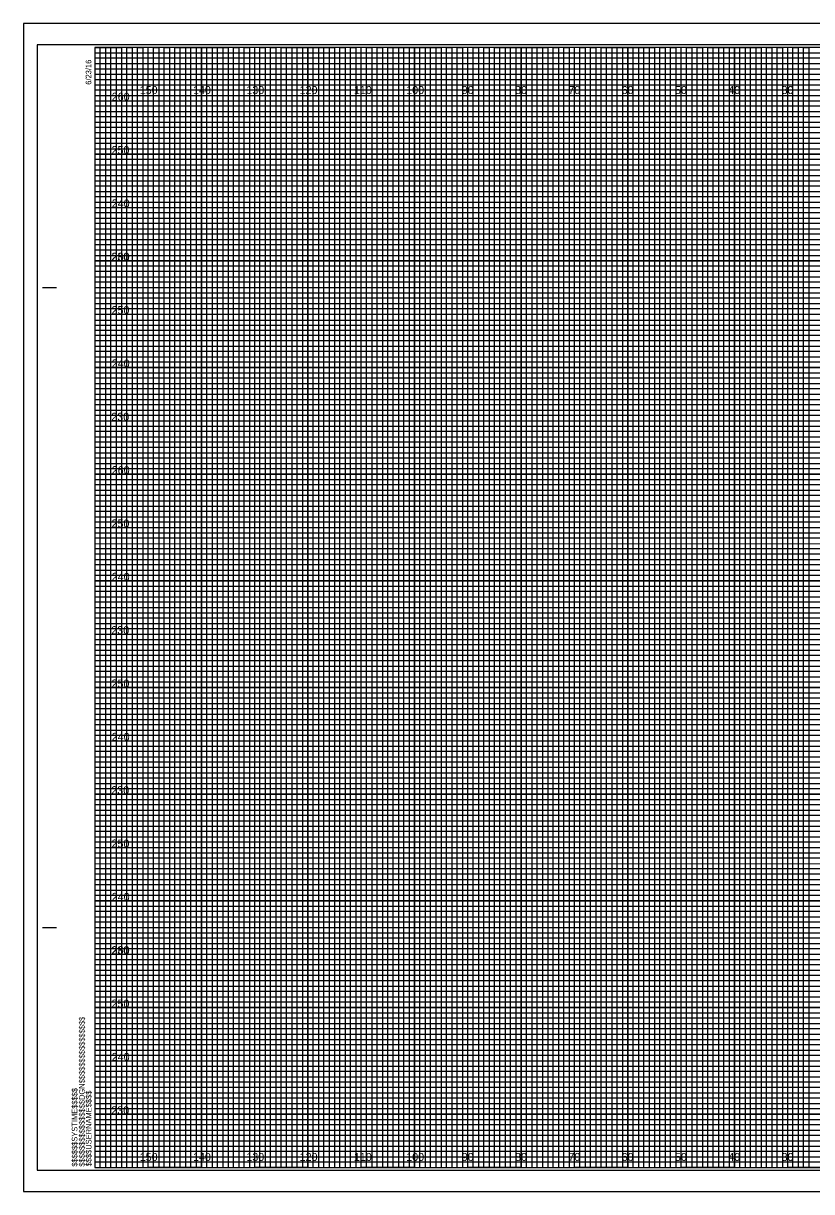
# Model space of a CAD drawing. Extents: x -13 to 359, y -5 to 2854.
# Drawn here: x -13.4 to 134.5, y 655.5 to 874.5 of the extents above; entities that cross this region are included whole.
import ezdxf

# ---------------------------------------------------------------- set-up
doc = ezdxf.new("R2010")
doc.units = 0
for name, color, linetype in [('Exist Cross Section Cell', 7, 'Continuous'), ('Exist XS Ground Line', 7, 'Continuous'), ('Prop CMT Concrete Structures', 7, 'Continuous'), ('Prop CMT DNC', 7, 'Continuous'), ('Prop CMT Pvmt Course 1', 7, 'Continuous'), ('Prop CMT Pvmt Course 1 CG', 7, 'Continuous'), ('Prop CMT Pvmt Course 2', 7, 'Continuous'), ('Prop CMT Shear Line', 7, 'Continuous'), ('Prop CMT Slope Grass', 7, 'Continuous'), ('Prop CMT Subgrade Earthwork', 7, 'Continuous'), ('Scratch_Level_0', 7, 'Continuous')]:
    doc.layers.add(name, color=color, linetype=linetype)

msp = doc.modelspace()

# ---------------------------------------------------------------- linework, layer by layer
at = {"layer": 'Exist XS Ground Line'}
for p, q in [((10, 870), (0, 870)), ((10, 660), (10, 870)), ((30, 870), (20, 870)), ((20, 870), (20, 660)), ((30, 660), (30, 870)), ((50, 870), (40, 870)), ((40, 870), (40, 660)), ((50, 660), (50, 870)), ((70, 870), (60, 870)), ((60, 870), (60, 660)), ((70, 660), (70, 870)), ((90, 870), (80, 870)), ((80, 870), (80, 660)), ((90, 660), (90, 870)), ((110, 870), (100, 870)), ((100, 870), (100, 660)), ((110, 660), (110, 870)), ((130, 870), (120, 870)), ((120, 870), (120, 660)), ((130, 660), (130, 870)), ((20, 660), (10, 660)), ((40, 660), (30, 660)), ((60, 660), (50, 660)), ((80, 660), (70, 660)), ((100, 660), (90, 660)), ((120, 660), (110, 660)), ((140, 660), (130, 660))]:
    msp.add_line(p, q, dxfattribs=at)
for points in [[(0, 860), (320, 860), (320, 850), (0, 850)], [(0, 840), (320, 840), (320, 830), (0, 830)], [(0, 820), (320, 820), (320, 810), (0, 810)], [(0, 800), (320, 800), (320, 790), (0, 790)], [(0, 780), (320, 780), (320, 770), (0, 770)], [(0, 760), (320, 760), (320, 750), (0, 750)], [(0, 740), (320, 740), (320, 730), (0, 730)], [(0, 720), (320, 720), (320, 710), (0, 710)], [(0, 700), (320, 700), (320, 690), (0, 690)], [(0, 680), (320, 680), (320, 670), (0, 670)]]:
    msp.add_lwpolyline(points, dxfattribs=at)
at = {"layer": 'Prop CMT Concrete Structures'}
for p, q in [((-9.8, 825), (-7.3, 825)), ((-9.7, 825), (-7.2, 825)), ((-9.8, 705), (-7.3, 705)), ((-9.7, 705), (-7.2, 705)), ((0, 660), (0, 660)), ((0, 660), (0, 660)), ((0, 660), (0, 660)), ((0, 660), (0, 660)), ((0, 660), (0, 660)), ((0, 660), (0, 660)), ((0, 660), (0, 660))]:
    msp.add_line(p, q, dxfattribs=at)
msp.add_lwpolyline([(320, 870), (0, 870), (0, 660), (320, 660)], close=True, dxfattribs=at)
at = {"layer": 'Prop CMT DNC'}
for p, q in [((323.3, 874.5), (-13.4, 874.5)), ((-13.4, 874.5), (-13.4, 655.5)), ((-13.4, 655.5), (323.3, 655.5))]:
    msp.add_line(p, q, dxfattribs=at)
at = {"layer": 'Prop CMT Pvmt Course 1'}
for p, q in [((0, 869), (260, 869)), ((260, 867.98), (0, 867.98)), ((0, 867.98), (0, 867)), ((0, 867), (260, 867)), ((260, 865.89), (0, 865.89)), ((0, 865.89), (0, 864)), ((0, 864), (320, 864))]:
    msp.add_line(p, q, dxfattribs=at)
for points in [[(0, 863), (270, 863), (320, 863), (320, 862), (0, 862)], [(0, 861), (320, 861), (320, 859), (0, 859)], [(0, 858), (320, 858), (320, 857), (0, 856.98)], [(0, 856), (320, 856), (320, 854), (0, 854)], [(0, 853), (320, 853), (320, 852), (0, 852)], [(0, 851), (320, 851), (320, 849), (0, 849)], [(0, 848), (320, 848), (320, 847), (0, 847)], [(0, 846), (320, 846), (320, 844), (0, 844)], [(0, 843), (320, 843), (320, 842), (0, 842)], [(0, 841), (320, 841), (320, 839), (0, 839)], [(0, 838), (320, 838), (320, 837), (0, 837)], [(0, 836), (320, 836), (320, 833.95), (320, 833), (320, 832), (0, 832)], [(0, 834), (320, 834), (320, 833), (0, 833)], [(0, 831), (320, 831), (320, 829), (0, 829.03)], [(0, 829.03), (320, 829), (320, 828), (0, 828)], [(0, 827), (320, 827), (320, 826), (0, 826)], [(0, 824), (320, 824), (320, 823), (0, 823)], [(0, 822), (320, 822), (320, 821), (0, 821)], [(-0.07, 818.89), (320, 818.89), (320, 817.88), (-0.07, 817.88)], [(0, 817), (320, 817), (320, 816), (0, 816)], [(0, 814), (320, 814), (320, 813), (0, 813)], [(0, 812), (320, 812), (320, 811), (0, 811)], [(0, 809), (320, 809), (320, 808), (0, 808)], [(0, 807), (320, 807), (320, 806), (0, 806)], [(0, 804), (320, 804), (320, 803), (0, 803)], [(0, 802), (320, 802), (320, 801), (0, 801)], [(0, 799), (320, 799), (319.99, 797.98), (0, 798)], [(0, 797), (320, 797), (320, 796), (0, 796)], [(0, 794), (320, 794), (320, 793), (0, 793)], [(0, 792), (320, 792), (320, 791), (0, 791)], [(0, 789), (320, 789), (320, 788), (0, 788)], [(0, 787), (320, 787), (320, 786), (0, 786)], [(0, 784), (320, 784), (320, 783), (0, 783)], [(0, 782), (320, 782), (320, 781), (0, 781)], [(0, 779), (320, 779), (320, 778), (0, 778)], [(0, 776.99), (320.07, 776.91), (320, 776), (0, 776)], [(0, 774), (320, 774), (320, 773), (0, 773)], [(0, 772), (320, 772), (320, 771), (0, 771)], [(0, 769), (320, 769), (320, 768), (0, 768)], [(0, 767), (320, 767), (320, 766), (0, 766)], [(0, 764), (320, 764), (320, 763), (0, 763)], [(0, 762), (320, 762), (320, 761), (0, 761)], [(0, 759), (320, 759), (320, 758), (0, 758)], [(0, 757), (320, 757), (320, 756), (0, 756)], [(0, 754), (320, 754), (320, 753), (0, 753)], [(0, 752), (320, 752), (320, 751), (0, 751)], [(0, 749), (320, 749), (320, 748), (0, 748)], [(0, 747), (320, 747), (320, 746), (0, 746)], [(0, 744), (320, 744), (320, 743), (0, 743)], [(0, 742), (320, 742), (320, 741), (0, 741)], [(0, 739), (320, 739), (319.99, 737.98), (0, 738)], [(0, 737), (320, 737), (320, 736), (0, 736)], [(0, 734), (320, 734), (320, 733), (0, 733)], [(0, 732), (320, 732), (320, 731), (0, 731)], [(0, 729), (320, 729), (320, 728), (0, 728)], [(0, 727), (320, 727), (320, 726), (0, 726)], [(0, 724), (320, 724), (320, 723), (0, 723)], [(0, 722), (320, 722), (320, 721), (0, 721)], [(0, 719), (320, 719), (320, 718), (0, 718)], [(0, 716.99), (320.07, 716.91), (320, 716), (0, 716)], [(0, 714), (320, 714), (320, 713), (0, 713)], [(0, 712), (320, 712), (320, 711), (0, 711)], [(0, 709), (320, 709), (320, 708), (0, 708)], [(0, 707), (320, 707), (320, 706), (0, 706)], [(0, 704), (320, 704), (320, 703), (0, 703)], [(0, 702), (320, 702), (320, 701), (0, 701)], [(0, 699), (320, 699), (320, 698), (0, 698)], [(0, 697), (320, 697), (320, 696), (0, 696)], [(0, 694), (320, 694), (320, 693), (0, 693)], [(0, 692), (320, 692), (320, 691), (0, 691)], [(0, 689), (320, 689), (320, 688), (0, 688)], [(0, 687), (320, 687), (320, 686), (0, 686)], [(0, 684), (320, 684), (320, 683), (0, 683)], [(0, 682), (320, 682), (320, 681), (0, 681)], [(0, 679), (320, 679), (320, 678), (0, 678)], [(0, 677), (320, 677), (320, 676), (0, 676)], [(0, 674), (320, 674), (320, 673), (0, 673)], [(0, 672), (320, 672), (320, 671), (0, 671)], [(0, 669), (320, 669), (320, 668), (0, 668)], [(0, 667), (320, 667), (320, 666), (0, 666)], [(0, 664), (320, 664), (320, 663), (0, 663)], [(0, 662), (320, 662), (320, 661), (0, 661)]]:
    msp.add_lwpolyline(points, dxfattribs=at)
at = {"layer": 'Prop CMT Pvmt Course 1 CG'}
for points in [[(0, 660), (1, 660), (1, 870), (2, 870), (2, 660)], [(2, 660), (3, 660), (3, 870), (4, 870), (4, 660)], [(5, 660), (6, 660), (6, 870), (7, 870), (7, 660)], [(7, 660), (8, 660), (8, 870), (9, 870), (9, 660)], [(10, 660), (11, 660), (11, 870), (12, 870), (12, 660)], [(12, 660), (13, 660), (13, 870), (14, 870), (14, 660)], [(15, 660), (16, 660), (16, 870), (17, 870), (17, 660)], [(17, 660), (18, 660), (18, 870), (19, 870), (19, 660)], [(20, 660), (21, 660), (21, 870), (22, 870), (22, 660)], [(22, 660), (23, 660), (23, 870), (24, 870), (24, 660)], [(25, 660), (26, 660), (26, 870), (27, 870), (27, 660)], [(27, 660), (28, 660), (28, 870), (29, 870), (29, 660)], [(30, 660), (31, 660), (31, 870), (32, 870), (32, 660)], [(32, 660), (33, 660), (33, 870), (34, 870), (34, 660)], [(35, 660), (36, 660), (36, 870), (37, 870), (37, 660)], [(37, 660), (38, 660), (38, 870), (39, 870), (39, 660)], [(40, 660), (41, 660), (41, 870), (42, 870), (42, 660)], [(42, 660), (43, 660), (43, 870), (44, 870), (44, 660)], [(45, 660), (46, 660), (46, 870), (47, 870), (47, 660)], [(47, 660), (48, 660), (48, 870), (49, 870), (49, 660)], [(50, 660), (51, 660), (51, 870), (52, 870), (52, 660)], [(52, 660), (53, 660), (53, 870), (54, 870), (54, 660)], [(55, 660), (56, 660), (56, 870), (57, 870), (57, 660)], [(57, 660), (58, 660), (58, 870), (59, 870), (59, 660)], [(60, 660), (61, 660), (61, 870), (62, 870), (62, 660)], [(62, 660), (63, 660), (63, 870), (64, 870), (64, 660)], [(65, 660), (66, 660), (66, 870), (67, 870), (67, 660)], [(67, 660), (68, 660), (68, 870), (69, 870), (69, 660)], [(70, 660), (71, 660), (71, 870), (72, 870), (72, 660)], [(72, 660), (73, 660), (73, 870), (74, 870), (74, 660)], [(75, 660), (76, 660), (76, 870), (77, 870), (77, 660)], [(77, 660), (78, 660), (78, 870), (79, 870), (79, 660)], [(80, 660), (81, 660), (81, 870), (82, 870), (82, 660)], [(82, 660), (83, 660), (83, 870), (84, 870), (84, 660)], [(85, 660), (86, 660), (86, 870), (87, 870), (87, 660)], [(87, 660), (88, 660), (88, 870), (89, 870), (89, 660)], [(90, 660), (91, 660), (91, 870), (92, 870), (92, 660)], [(92, 660), (93, 660), (93, 870), (94, 870), (94, 660)], [(95, 660), (96, 660), (96, 870), (97, 870), (97, 660)], [(97, 660), (98, 660), (98, 870), (99, 870), (99, 660)], [(100, 660), (101, 660), (101, 870), (102, 870), (102, 660)], [(102, 660), (103, 660), (103, 870), (104, 870), (104, 660)], [(105, 660), (106, 660), (106, 870), (107, 870), (107, 660)], [(107, 660), (108, 660), (108, 870), (109, 870), (109, 660)], [(110, 660), (111, 660), (111, 870), (112, 870), (112, 660)], [(112, 660), (113, 660), (113, 870), (114, 870), (114, 660)], [(115, 660), (116, 660), (116, 870), (117, 870), (117, 660)], [(117, 660), (118, 660), (118, 870), (119, 870), (119, 660)], [(120, 660), (121, 660), (121, 870), (122, 870), (122, 660)], [(122, 660), (123, 660), (123, 870), (124, 870), (124, 660)], [(125, 660), (126, 660), (126, 870), (127, 870), (127, 660)], [(127, 660), (128, 660), (128, 870), (129, 870), (129, 660)], [(130, 660), (131, 660), (131, 870), (132, 870), (132, 660)], [(132, 660), (133, 660), (133, 870), (134, 870), (134, 660)]]:
    msp.add_lwpolyline(points, dxfattribs=at)
at = {"layer": 'Prop CMT Shear Line'}
for p, q in [((10, 660), (10, 870)), ((20, 660), (20, 870)), ((30, 660), (30, 870)), ((40, 660), (40, 870)), ((50, 660), (50, 870)), ((60, 660), (60, 870)), ((70, 660), (70, 870)), ((80, 660), (80, 870)), ((90, 660), (90, 870)), ((100, 660), (100, 870)), ((110, 660), (110, 870)), ((120, 660), (120, 870)), ((130, 660), (130, 870)), ((0, 860), (320, 860)), ((0, 850), (320, 850)), ((0, 840), (320, 840)), ((0, 830), (320, 830)), ((0, 820), (320, 820)), ((0, 810), (320, 810)), ((0, 800), (320, 800)), ((0, 790), (320, 790)), ((0, 780), (320, 780)), ((0, 770), (320, 770)), ((0, 760), (320, 760)), ((0, 750), (320, 750)), ((0, 740), (320, 740)), ((0, 730), (320, 730)), ((0, 720), (320, 720)), ((0, 710), (320, 710)), ((0, 700), (320, 700)), ((0, 690), (320, 690)), ((0, 680), (320, 680)), ((0, 670), (320, 670))]:
    msp.add_line(p, q, dxfattribs=at)
at = {"layer": 'Prop CMT Slope Grass'}
msp.add_lwpolyline([(-10.8, 659.5), (322.4, 659.5), (322.4, 870.5), (-10.8, 870.5)], close=True, dxfattribs=at)
at = {"layer": 'Prop CMT Subgrade Earthwork'}
msp.add_lwpolyline([(-13.4, 655.5), (323.3, 655.5), (323.3, 874.5), (-13.4, 874.5)], close=True, dxfattribs=at)
at = {"layer": 'Scratch_Level_0'}
for points in [[(0, 870), (5, 870), (5, 660), (15, 660), (15, 870), (25, 870), (25, 660), (35, 660), (35, 870), (45, 870), (45, 660), (55, 660), (55, 870), (65, 870), (65, 660), (75, 660), (75, 870), (85, 870), (85, 660), (95, 660), (95, 870), (105, 870), (105, 660), (115, 660), (115, 870), (125, 870), (125, 660), (135, 660)], [(0, 865), (275, 865)], [(0, 845), (320, 845), (320, 855), (0, 855)], [(0, 825), (320, 825), (320, 835), (0, 835)], [(0, 805), (320, 805), (320, 815), (0, 815)], [(0, 785), (320, 785), (320, 795), (0, 795)], [(0, 765), (320, 765), (320, 775), (0, 775)], [(0, 745), (320, 745), (320, 755), (0, 755)], [(0, 725), (320, 725), (320, 735), (0, 735)], [(0, 705), (320, 705), (320, 715), (0, 715)], [(0, 685), (320, 685), (320, 695), (0, 695)], [(0, 665), (320, 665), (320, 675), (0, 675)]]:
    msp.add_lwpolyline(points, dxfattribs=at)

# ---------------------------------------------------------------- texts
at = {"layer": 'Exist Cross Section Cell'}
for s, p in [('150', (8.44, 861.25)), ('140', (18.44, 861.25)), ('130', (28.44, 861.25)), ('120', (38.44, 861.25)), ('110', (48.62, 861.25)), ('100', (58.44, 861.25)), ('90', (68.86, 861.25)), ('80', (78.86, 861.25)), ('70', (88.86, 861.25)), ('60', (98.86, 861.25)), ('50', (108.86, 861.25)), ('40', (118.86, 861.25)), ('30', (128.86, 861.25)), ('150', (8.44, 661.25)), ('140', (18.44, 661.25)), ('130', (28.44, 661.25)), ('120', (38.44, 661.25)), ('110', (48.62, 661.25)), ('100', (58.44, 661.25)), ('90', (68.86, 661.25)), ('80', (78.86, 661.25)), ('70', (88.86, 661.25)), ('60', (98.86, 661.25)), ('50', (108.86, 661.25)), ('40', (118.86, 661.25)), ('30', (128.86, 661.25))]:
    msp.add_text(s, height=1.5, dxfattribs=at).set_placement(p)
at = {"layer": 'Prop CMT Concrete Structures'}
for s, p in [('6/23/16', (-0.65, 863)), ('$$$$$$$$$$$$$$$$DGN$$$$$$$$$$$$$$$$', (-1.88, 660.18)), ('$$$$$$SYSTIME$$$$$', (-3.26, 660.18)), ('$$$$USERNAME$$$$', (-0.62, 660.23))]:
    msp.add_text(s, height=1.05, rotation=90, dxfattribs=at).set_placement(p)
at = {"layer": 'Prop CMT Pvmt Course 2'}
for s, p in [('260', (3.19, 860)), ('250', (3.15, 850)), ('240', (3.19, 840)), ('230', (3.11, 830)), ('260', (3.19, 830)), ('250', (3.15, 820)), ('240', (3.19, 810)), ('230', (3.11, 800)), ('260', (3.19, 790)), ('250', (3.15, 780)), ('240', (3.19, 770)), ('230', (3.11, 760)), ('250', (3.15, 750)), ('240', (3.19, 740)), ('230', (3.11, 730)), ('250', (3.15, 720)), ('240', (3.19, 710)), ('230', (3.11, 700)), ('260', (3.19, 700)), ('250', (3.15, 690)), ('240', (3.19, 680)), ('230', (3.11, 670))]:
    msp.add_text(s, height=1.5, dxfattribs=at).set_placement(p)

doc.saveas('drawing.dxf')
